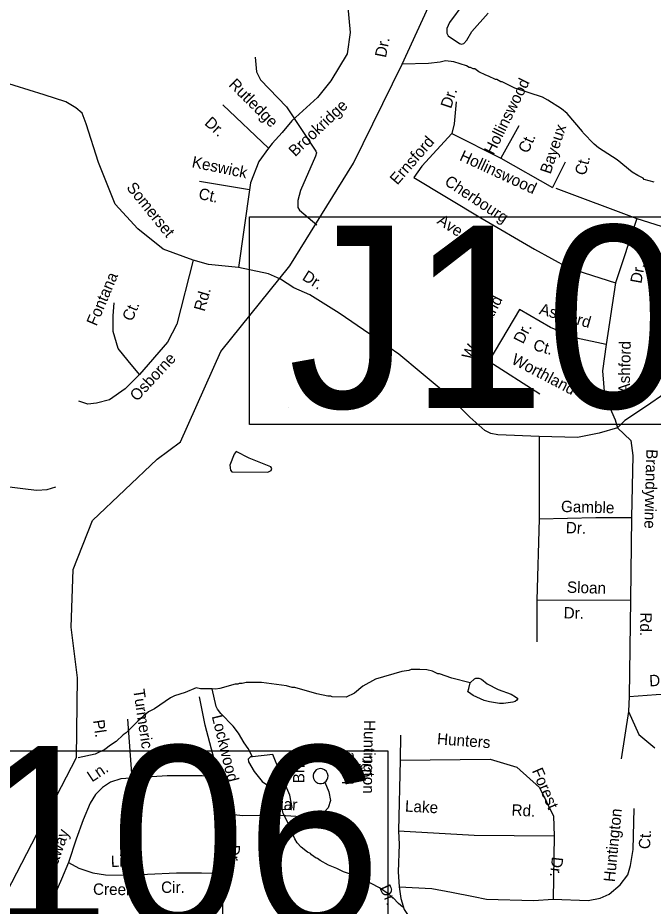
# Model space of a CAD drawing. Extents: x 1551653 to 1702041, y 811336 to 920032.
# Drawn here: x 1602815 to 1606474, y 836287 to 841407 of the extents above; entities that cross this region are included whole.
import ezdxf

# ---------------------------------------------------------------- set-up
doc = ezdxf.new("R2010")
doc.units = 0
for name, color, linetype in [('Old_Level_10', 7, 'Continuous'), ('Old_Level_35', 7, 'Continuous'), ('Old_Level_4', 7, 'Continuous'), ('Old_Level_59', 7, 'Continuous'), ('Old_Level_62', 7, 'Continuous')]:
    doc.layers.add(name, color=color, linetype=linetype)

msp = doc.modelspace()

# ---------------------------------------------------------------- linework, layer by layer
at = {"layer": 'Old_Level_35'}
for p, q in [((1604258.199, 840655.22), (1603996.067, 840905.846)), ((1605701.312, 840783.414), (1605597.158, 840598.106)), ((1605315.555, 840740.948), (1605597.158, 840598.106)), ((1605597.158, 840598.106), (1605894.189, 840428.241)), ((1605967.483, 840574.943), (1605894.189, 840428.241)), ((1604149.243, 840415.068), (1603862.51, 840463.852)), ((1604149.243, 840415.068), (1604086.162, 839967.414)), ((1605913.477, 840424.38), (1606380.242, 840250.654)), ((1606380.242, 840250.654), (1606256.8, 839880.039)), ((1606380.242, 840250.654), (1607005.167, 840049.904)), ((1606256.8, 839880.039), (1606202.794, 839524.865)), ((1605705.169, 839725.615), (1605527.721, 839428.351)), ((1605527.721, 839428.351), (1605820.896, 839239.182)), ((1605818.185, 838994.116), (1605818.185, 838518.936)), ((1605818.185, 838518.936), (1605804.012, 838050.847)), ((1606349.801, 838526.974), (1606342.715, 838051.793)), ((1605804.012, 838050.847), (1606342.715, 838051.793)), ((1605804.012, 838050.847), (1605804.125, 837810.657)), ((1606342.715, 838051.793), (1606335.628, 837495.052)), ((1606335.628, 837495.052), (1606331.853, 837408.421)), ((1606331.853, 837408.421), (1606289.333, 837135.369)), ((1603447.657, 837365.028), (1603472.255, 837024.517)), ((1605019.2, 837273.262), (1605016.327, 837128.353)), ((1605016.327, 837128.353), (1605008.456, 836721.423)), ((1605903.157, 836692.545), (1605897.909, 836327.621))]:
    msp.add_line(p, q, dxfattribs=at)
for points in [[(1604653.468, 841678.835), (1604714.44, 841488.094), (1604728.483, 841321.791), (1604712.099, 841199.991), (1604618.481, 841043.058), (1604541.245, 840947.023), (1604393.946, 840812.154), (1604337.775, 840746.569), (1604279.263, 840683.327), (1604258.199, 840655.22)], [(1603825.234, 840010.458), (1603653.194, 840073.589), (1603506.96, 840191.242), (1603375.063, 840331.851), (1603280.441, 840572.895), (1603208.758, 840796.723), (1603185.819, 840856.983), (1603148.544, 840888.549), (1603091.196, 840922.984), (1602967.901, 840963.158), (1602619.942, 841070.768)], [(1605338.701, 840922.395), (1605327.128, 840794.996), (1605315.555, 840740.948)], [(1605315.555, 840740.948), (1605141.965, 840551.78), (1605095.675, 840486.149)], [(1604258.199, 840655.22), (1604203.723, 840578.634), (1604154.978, 840455.243), (1604149.243, 840415.068)], [(1605095.675, 840486.149), (1605481.43, 840254.515), (1605790.035, 840073.068), (1605986.771, 839964.972), (1606256.8, 839880.039)], [(1603825.234, 840010.458), (1603730.861, 839641.377), (1603676.382, 839538.073), (1603515.812, 839351.55)], [(1604086.162, 839967.414), (1603914.122, 839984.632), (1603825.234, 840010.458)], [(1605818.185, 838994.116), (1605579.335, 839002.981), (1605538.459, 839010.212), (1605503.801, 839027.925), (1605418.919, 839105.091), (1605298.719, 839226.596), (1605138.749, 839360.513), (1605010.262, 839468.18), (1604841.925, 839584.256), (1604665.669, 839704.499), (1604497.333, 839810.572), (1604404.005, 839849.856), (1604328.799, 839900.811), (1604258.451, 839931.204), (1604086.162, 839967.414)], [(1603515.812, 839351.55), (1603449.863, 839429.029), (1603392.516, 839500.768), (1603363.843, 839598.334), (1603363.843, 839690.16), (1603369.578, 839764.769)], [(1606202.794, 839524.865), (1606033.061, 839559.611), (1605882.617, 839621.38), (1605705.169, 839725.615)], [(1607109.089, 839589.394), (1606970.259, 839518.092), (1606804.028, 839406.567), (1606646.038, 839313.976), (1606435.966, 839169.543), (1606311.748, 839085.443)], [(1606202.794, 839524.865), (1606182.73, 839372.187), (1606194.303, 839229.346), (1606256.024, 839090.365), (1606269.134, 839044.018)], [(1603515.812, 839351.55), (1603432.659, 839268.332), (1603343.771, 839205.201), (1603269.221, 839185.114), (1603217.609, 839179.375), (1603165.997, 839196.593)], [(1606311.748, 839085.443), (1606269.134, 839044.018), (1606162.858, 839013.355), (1606037.742, 838988.544), (1605818.185, 838994.116)], [(1606269.134, 839044.018), (1606346.258, 838970.239), (1606356.888, 838885.133), (1606349.801, 838526.974)], [(1602408.115, 838749.737), (1602654.504, 838718.911), (1602782.098, 838701.296), (1602874.493, 838690.288), (1602925.091, 838683.682), (1602984.488, 838688.085), (1603035.086, 838703.498)], [(1605818.185, 838518.936), (1606144.287, 838526.974), (1606349.801, 838526.974)], [(1606335.628, 837495.052), (1606491.304, 837507.713), (1606948.397, 837521.897), (1607163.299, 837489.818)], [(1603969.768, 837034.911), (1603947.022, 837127.024), (1603893.702, 837329.618), (1603861.819, 837493.959)], [(1606331.853, 837408.421), (1606392.09, 837277.215), (1606484.218, 837199.2)], [(1605016.327, 837128.353), (1605535.831, 837133.604), (1605688.514, 837088.18), (1605819.196, 836970.832), (1605900.533, 836805.435), (1605903.157, 836692.545)], [(1604582.608, 837001.069), (1604591.158, 837008.1), (1604596.949, 837017.388), (1604600.748, 837027.116), (1604601.965, 837037.897), (1604598.858, 837052.368), (1604592.28, 837063.507), (1604581.48, 837073.533), (1604568.369, 837078.402), (1604557.799, 837080.016), (1604543.534, 837077.303), (1604534.022, 837072.093), (1604524.826, 837062.673), (1604518.816, 837052.391), (1604516.207, 837042.237), (1604515.997, 837031.837), (1604518.202, 837022.185), (1604523.002, 837012.083), (1604530.837, 837003.72), (1604542.694, 836996.476), (1604552.451, 836994.075), (1604563.862, 836994.245), (1604575.315, 836996.614), (1604582.608, 837001.069)], [(1603969.768, 837034.911), (1603875.982, 837038.015), (1603676.288, 837038.664), (1603408.368, 837020.088), (1603348.146, 837000.895), (1603303.73, 836971.581), (1603263.264, 836929.977), (1603232.644, 836880.571), (1603191.489, 836785.151), (1603152.208, 836673.685), (1603106.437, 836538.337)], [(1603997.039, 836820.64), (1603990.424, 836928.635), (1603969.768, 837034.911)], [(1604582.608, 837001.069), (1604605.722, 836946.768), (1604615.108, 836896.552), (1604602.615, 836852.779), (1604578.278, 836827.057), (1604546.106, 836809.501), (1604476.086, 836800.515), (1604328.406, 836810.315), (1604108.623, 836807.169), (1603997.039, 836820.64)], [(1603994.427, 836474.899), (1603994.755, 836658.796), (1603997.039, 836820.64)], [(1605897.909, 836327.621), (1606099.938, 836319.744), (1606168.155, 836332.871), (1606220.631, 836356.5), (1606283.601, 836409.007), (1606328.204, 836466.764), (1606343.947, 836521.897), (1606359.69, 836613.784), (1606364.937, 836850.066)], [(1605008.456, 836721.423), (1605011.08, 836642.663), (1605005.832, 836485.142), (1605011.08, 836398.505)], [(1605008.456, 836721.423), (1605443.999, 836695.17), (1605903.157, 836692.545)], [(1603106.437, 836538.337), (1603067.28, 836442.878), (1602997.218, 836283.81), (1602953.409, 836146.422), (1602932.667, 836080.805), (1602928.137, 836044.877), (1602932.011, 836028.791), (1602937.421, 836019.273), (1602945.696, 836012.702), (1602959.81, 836008.214), (1603015.548, 836003.683), (1603150.984, 835982.124), (1603302.778, 835968.037), (1603348.999, 835957.896), (1603380.353, 835945.051), (1603393.578, 835935.98), (1603402.706, 835922.387), (1603409.264, 835870.825), (1603417.88, 835762.791), (1603426.735, 835676.561), (1603437.227, 835562.486), (1603427.486, 835476.833)], [(1603106.437, 836538.337), (1603165.803, 836505.516), (1603247.499, 836478.446), (1603321.118, 836467.547), (1603434.947, 836466.038), (1603562.906, 836470.447), (1603728.752, 836478.288), (1603872.633, 836478.37), (1603994.427, 836474.899)], [(1603978.107, 835527.15), (1603989.155, 835613.323), (1603993.649, 835805.34), (1603994.955, 836057.055), (1603996.464, 836318.971), (1603994.427, 836474.899)], [(1605011.08, 836398.505), (1605199.991, 836388.004), (1605312.812, 836367.001), (1605438.752, 836343.373), (1605514.841, 836327.621), (1605785.088, 836319.744), (1605897.909, 836327.621)], [(1605011.08, 836398.505), (1605021.575, 836330.245), (1605039.941, 836267.237), (1605123.901, 836142.796), (1605165.881, 836061.41), (1605184.247, 836029.906), (1605194.743, 835987.9), (1605202.614, 835877.635)]]:
    msp.add_lwpolyline(points, dxfattribs=at)
at = {"layer": 'Old_Level_4'}
msp.add_line((1604371.792, 839158.632), (1604371.792, 839158.632), dxfattribs=at)
for points in [[(1604149.59, 840259.415), (1607452.654, 840259.415), (1607452.654, 839062.663), (1604149.59, 839062.663), (1604149.59, 840259.415)], [(1601700.768, 837182.053), (1604946.882, 837182.053), (1604946.882, 836099.278), (1601700.768, 836099.278), (1601700.768, 837182.053)]]:
    msp.add_lwpolyline(points, dxfattribs=at)
at = {"layer": 'Old_Level_59'}
msp.add_lwpolyline([(1602691.698, 836256.223), (1603153.68, 837143.022), (1603159.626, 837602.492), (1603121.692, 837895.409), (1603133.687, 838226.722), (1603245.646, 838510.052), (1603617.61, 838863.562), (1603752.637, 838962.654), (1603984.653, 839483.179), (1604382.66, 839977.303), (1604748.41, 840569.032), (1605029.243, 841139.041), (1605298.752, 841731.999), (1605693.027, 842516.682)], dxfattribs=at)
at = {"layer": 'Old_Level_62'}
for points in [[(1605383.611, 841490.331), (1605300.463, 841380.372), (1605284.981, 841345.769), (1605285.391, 841318.19), (1605293.696, 841303.631), (1605358.8, 841258.315), (1605371.206, 841254.214), (1605383.099, 841259.34), (1605400.323, 841277.487), (1605429.03, 841328.391), (1605523.97, 841434.249)], [(1604182.426, 841180.958), (1604189.09, 841094.786), (1604211.954, 841049.982), (1604361.949, 840893.527), (1604531.527, 840638.34), (1604534.501, 840627.728), (1604529.682, 840608.915), (1604442.74, 840412.475), (1604427.053, 840354.188), (1604428.079, 840312.973), (1604437.306, 840298.927), (1604537.576, 840213.574)], [(1606480.752, 840460.098), (1606423.03, 840474.913), (1606417.186, 840482.961), (1606385.403, 840497.417), (1606353.62, 840517.872), (1606266.678, 840589.076), (1606159.641, 840656.538), (1606134.009, 840678.888), (1606070.956, 840743.736), (1606067.06, 840751.784), (1605978.477, 840855.028), (1605946.899, 840881.429), (1605867.647, 840932.538), (1605835.864, 840948.994), (1605676.641, 841001.179), (1605605.18, 841038.191), (1605597.183, 841038.294), (1605573.397, 841050.597), (1605565.4, 841050.75), (1605525.722, 841071.307), (1605509.728, 841075.511), (1605470.051, 841096.067), (1605446.265, 841112.368), (1605438.268, 841112.471), (1605422.376, 841120.725), (1605414.482, 841120.827), (1605398.59, 841131.028), (1605326.924, 841154.046), (1605279.045, 841158.71), (1605246.954, 841151.175), (1605180.927, 841144.101), (1605029.243, 841139.041)], [(1604147.872, 838868.94), (1604073.336, 838907.336), (1604061.34, 838891.189), (1604037.144, 838828.186), (1604040.015, 838799.633), (1604047.192, 838790.508), (1604255.935, 838788.15), (1604274.082, 838798.351), (1604277.773, 838810.09), (1604272.954, 838819.625), (1604147.872, 838868.94)], [(1605420.428, 837574.912), (1605314.416, 837601.006), (1605242.853, 837626.022), (1605234.856, 837626.125), (1605203.073, 837640.581), (1605171.187, 837648.988), (1605131.202, 837651.551), (1605081.272, 837650.269), (1605067.226, 837644.425), (1605027.138, 837638.991), (1604874.579, 837595.162), (1604802.094, 837554.151), (1604753.599, 837514.832), (1604705.309, 837491.508), (1604625.339, 837492.636), (1604617.444, 837496.737), (1604601.45, 837496.993), (1604537.679, 837509.86), (1604410.239, 837547.641), (1604394.245, 837547.846), (1604362.359, 837556.304), (1604218.72, 837576.297), (1604130.753, 837575.528), (1604106.762, 837569.889), (1604090.768, 837570.094), (1604082.668, 837566.198), (1604066.674, 837566.403), (1603978.399, 837541.643), (1603954.408, 837538.003), (1603935.133, 837539.183)], [(1605420.428, 837574.912), (1605444.317, 837597.212), (1605452.314, 837601.108), (1605470.358, 837600.852), (1605486.25, 837594.597), (1605517.828, 837568.197), (1605581.394, 837535.287), (1605655.52, 837508.425), (1605680.947, 837493.609), (1605694.07, 837483.408), (1605689.559, 837473.463), (1605679.409, 837465.774), (1605666.388, 837462.134), (1605612.254, 837454.906), (1605588.263, 837455.214), (1605532.489, 837463.979), (1605500.603, 837472.438), (1605437.037, 837501.299), (1605411.303, 837519.703), (1605406.485, 837522.676), (1605411.611, 837541.694), (1605420.428, 837574.912)], [(1603935.133, 837539.183), (1603866.441, 837539.233), (1603842.552, 837545.539), (1603778.166, 837518.472), (1603717.983, 837499.3), (1603693.787, 837487.663), (1603603.051, 837424.917), (1603568.808, 837407.385), (1603506.062, 837352.278), (1603439.215, 837285.226), (1603421.068, 837273.486), (1603382.62, 837236.064), (1603348.274, 837214.533), (1603315.979, 837188.954), (1603261.64, 837163.732), (1603163.727, 837142.663)], [(1604167.15, 837148.404), (1604141.621, 837195.464), (1604118.04, 837227.759), (1604086.872, 837284.2), (1604055.396, 837324.646), (1603984.448, 837397.594), (1603964.763, 837421.893), (1603956.971, 837437.989), (1603935.133, 837539.183)], [(1604167.15, 837148.404), (1604155.052, 837146.764), (1604141.416, 837134.768), (1604143.261, 837118.518), (1604175.659, 837063.308), (1604221.591, 837004.919), (1604292.232, 836957.245), (1604303.92, 836943.044), (1604320.221, 836860.921), (1604329.859, 836846.773), (1604338.266, 836845.645)], [(1604338.266, 836845.645), (1604354.772, 836843.389), (1604385.838, 836846.414), (1604394.758, 836855.077), (1604382.66, 836926.128), (1604324.117, 837061.154), (1604284.029, 837160.144), (1604167.15, 837148.404)], [(1605032.572, 836281.239), (1605006.838, 836301.591), (1604977.311, 836333.989), (1604969.416, 836338.09), (1604953.627, 836354.34), (1604898.16, 836393.095), (1604802.914, 836442.41), (1604794.917, 836442.512), (1604731.351, 836471.425), (1604691.57, 836483.933), (1604651.893, 836504.49), (1604604.116, 836523.149), (1604556.544, 836549.806), (1604540.755, 836562.058), (1604532.758, 836564.16), (1604507.024, 836582.512), (1604501.077, 836590.56), (1604483.238, 836598.814), (1604447.661, 836627.316), (1604423.978, 836651.665), (1604410.342, 836675.811), (1604375.483, 836756.294), (1604363.795, 836780.438), (1604344.315, 836820.731), (1604338.266, 836845.645)]]:
    msp.add_lwpolyline(points, dxfattribs=at)

# ---------------------------------------------------------------- texts
at = {"layer": 'Old_Level_10'}
for s, height, rotation, p in [('Dr.', 65.6167, 78.694364, (1604934.874, 841173.923)), ('Rutledge', 65.6167, 315.122153, (1604025.651, 841017.617)), ('Hollinswood', 65.61666, 63.759181, (1605555.327, 840612.959)), ('Dr.', 65.6167, 71.502908, (1605309.609, 840879.944)), ('Brookridge', 65.6167, 43.423475, (1604412.317, 840602.87)), ('Dr.', 65.6167, 317.864308, (1603885.9, 840794.919)), ('Bayeux', 65.6167, 71.746442, (1605882.901, 840502.446)), ('Ernsford', 65.6167, 48.947781, (1605000.423, 840439.822)), ('Ct.', 65.6167, 65.483019, (1605752.951, 840621.356)), ('Hollinswood', 65.61666, 335.194356, (1605354.046, 840587.735)), ('Keswick', 65.6167, 348.265714, (1603813.89, 840546.778)), ('Ct.', 65.6167, 75.944689, (1606084.85, 840494.543)), ('Cherbourg', 65.6167, 326.45435, (1605267.352, 840449.084)), ('Somerset', 65.6167, 308.986886, (1603437.559, 840426.832)), ('Ct.', 65.6167, 348.265714, (1603852.225, 840363.604)), ('Ave.', 65.6167, 326.45435, (1605225.079, 840225.107)), ('Dr.', 65.6167, 79.598122, (1606405.723, 839872.292)), ('Fontana', 65.6167, 67.035169, (1603268.325, 839626.404)), ('Dr.', 65.6167, 327.929556, (1604448.227, 839899.839)), ('Rd.', 65.6167, 74.208478, (1603890.783, 839710.852)), ('Worthland', 65.6167, 62.912347, (1605426.426, 839429.345)), ('Ct.', 65.6167, 67.035169, (1603473.973, 839653.195)), ('Ashford', 65.6167, 344.221253, (1605813.771, 839700.425)), ('Dr.', 65.6167, 62.912347, (1605724.418, 839523.171)), ('Ct.', 65.6167, 344.221253, (1605778.254, 839493.446)), ('Ashford', 65.6167, 88.713353, (1606338.603, 839241.111)), ('Osborne', 65.6167, 47.138672, (1603501.864, 839192.502)), ('Worthland', 65.6167, 332.2038, (1605652.493, 839417.24)), ('Ct.', 65.6167, 332.2038, (1605550.447, 839227.097)), ('Brandywine', 65.6167, 268.455672, (1606435.111, 838921.383)), ('Gamble', 65.6167, 358.439556, (1605942.629, 838558.766)), ('Dr.', 65.6167, 358.439556, (1605970.215, 838436.39)), ('Sloan', 65.6167, 358.570778, (1605977.095, 838093.072)), ('Dr.', 65.6167, 358.570778, (1605957.826, 837945.505)), ('Rd.', 65.6167, 268.947444, (1606400.73, 837980.168)), ('Densmore', 65.6167, 2.838464, (1606452.723, 837553.462)), ('Turmeric', 65.6167, 278.372486, (1603479.719, 837533.19)), ('Lockwood', 65.6167, 283.870944, (1603931.491, 837381.278)), ('Pl.', 65.6167, 278.372486, (1603247.991, 837357.076)), ('Huntington', 65.6167, 269.315647, (1604808.923, 837359.764)), ('Hunters', 65.6167, 355.677111, (1605227.982, 837220.361)), ('Briar', 65.6167, 89.447889, (1604465.435, 836994.909)), ('Lake', 65.6167, 89.447889, (1604747.958, 836986.23)), ('Cir.', 65.6167, 89.447889, (1604849.202, 837028.198)), ('Ln.', 65.6167, 33.685481, (1603242.167, 836999.411)), ('Forest', 65.6167, 293.212264, (1605774.051, 837067.384)), ('Briar', 65.6167, 356.965725, (1604238.245, 836848.478)), ('Lake', 65.6167, 356.965725, (1605043.781, 836832.103)), ('Rd.', 65.6167, 356.965725, (1605657.181, 836809.548)), ('Huntington', 65.6167, 84.416269, (1606253.01, 836424.184)), ('Caraway', 65.6167, 70.460817, (1602996.969, 836390.044)), ('Ct.', 65.6167, 86.394617, (1606455.47, 836613.865)), ('Dr.', 65.6167, 270.943883, (1604028.111, 836640.182)), ('Little', 65.6167, 1.973619, (1603351.949, 836512.321)), ('Dr.', 65.6167, 263.769142, (1605891.629, 836573.511)), ('Creek', 65.6167, 359.240394, (1603248.026, 836352.806)), ('Cir.', 65.6167, 0.032661, (1603640.601, 836363.446)), ('Dr.', 65.6167, 294.446783, (1604896.402, 836392.931))]:
    msp.add_text(s, height=height, rotation=rotation, dxfattribs=at).set_placement(p)
at = {"layer": 'Old_Level_4'}
for s, p in [('J105', (1604371.792, 839158.632)), ('J106', (1601865.338, 836159.9))]:
    msp.add_text(s, height=1049.8646, dxfattribs=at).set_placement(p)

doc.saveas('drawing.dxf')
